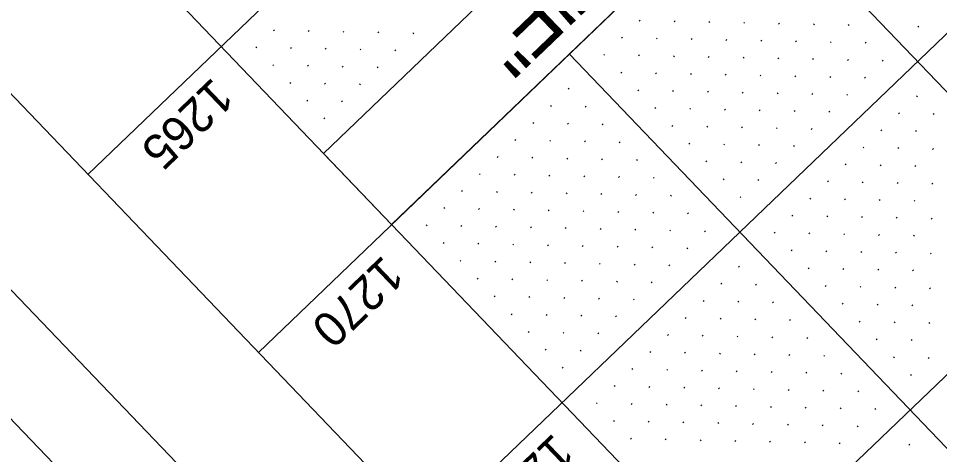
# Model space of a CAD drawing. Extents: x 2148987 to 2151117, y 142806 to 144993.
# Drawn here: x 2149110.7 to 2149297.8, y 143537.7 to 143626.2 of the extents above; entities that cross this region are included whole.
import ezdxf

# ---------------------------------------------------------------- set-up
doc = ezdxf.new("R2010")
doc.units = 0
for name, color, linetype in [('BASELINE', 7, 'Continuous'), ('PR_ABUT_PH3', 7, 'Continuous'), ('PR_PIER_PH3', 7, 'Continuous'), ('PR_Road_Concrete', 7, 'Continuous'), ('PR_Storm_Flow_Line', 7, 'Continuous'), ('SHT_Profile_Grid_Minor', 7, 'Continuous'), ('Wall D Bore', 7, 'Continuous')]:
    doc.layers.add(name, color=color, linetype=linetype)

msp = doc.modelspace()

# ---------------------------------------------------------------- linework, layer by layer
at = {"layer": 'BASELINE'}
msp.add_lwpolyline([(2151029.45, 144024.32), (2149802.07, 142848.08), (2149040.98, 143642.27), (2150268.36, 144818.51)], close=True, dxfattribs=at)
at = {"layer": 'PR_ABUT_PH3'}
msp.add_lwpolyline([(2151117.11, 144051.19), (2149817.52, 142805.76), (2148987.24, 143672.15), (2150286.82, 144917.58)], close=True, dxfattribs=at)
at = {"layer": 'PR_PIER_PH3'}
for p, q in [((2150261.97, 144684.26), (2149124.83, 143594.52)), ((2150296.56, 144648.16), (2149159.43, 143558.42)), ((2150331.16, 144612.07), (2149194.02, 143522.32)), ((2150365.75, 144575.97), (2149228.62, 143486.22)), ((2149258.7, 143653.55), (2149504.33, 143397.25)), ((2149222.6, 143618.96), (2149468.23, 143362.65))]:
    msp.add_line(p, q, dxfattribs=at)
at = {"layer": 'PR_Road_Concrete'}
msp.add_line((2149134.61, 143638.51), (2149463.26, 143295.57), dxfattribs=at)
for points in [[(2150941.76, 143974.91), (2149804.63, 142885.16), (2149078.13, 143643.25), (2150215.26, 144733)], [(2149294.8, 143688.15), (2149280.96, 143702.59), (2149172.66, 143598.8), (2149186.5, 143584.36)]]:
    msp.add_lwpolyline(points, close=True, dxfattribs=at)
at = {"layer": 'SHT_Profile_Grid_Minor'}
for p, q in [((2149236.98, 143625.81), (2149236.8, 143625.64)), ((2149244.05, 143625.66), (2149243.87, 143625.49)), ((2149251.12, 143625.51), (2149250.94, 143625.34)), ((2149258.19, 143625.36), (2149258.01, 143625.19)), ((2149265.26, 143625.21), (2149265.08, 143625.04)), ((2149272.33, 143625.06), (2149272.15, 143624.89)), ((2149279.4, 143624.91), (2149279.22, 143624.74)), ((2149293.54, 143624.61), (2149293.36, 143624.44)), ((2149162.68, 143623.86), (2149162.5, 143623.69)), ((2149169.75, 143623.71), (2149169.57, 143623.54)), ((2149176.82, 143623.56), (2149176.63, 143623.39)), ((2149183.88, 143623.41), (2149183.7, 143623.23)), ((2149190.95, 143623.26), (2149190.77, 143623.08)), ((2149233.37, 143622.35), (2149233.19, 143622.18)), ((2149240.44, 143622.2), (2149240.26, 143622.03)), ((2149247.51, 143622.05), (2149247.33, 143621.88)), ((2149254.58, 143621.9), (2149254.4, 143621.73)), ((2149261.65, 143621.75), (2149261.47, 143621.58)), ((2149268.72, 143621.6), (2149268.54, 143621.43)), ((2149275.79, 143621.45), (2149275.61, 143621.28)), ((2149282.86, 143621.3), (2149282.68, 143621.13)), ((2149159.07, 143620.4), (2149158.89, 143620.23)), ((2149166.14, 143620.25), (2149165.96, 143620.08)), ((2149173.21, 143620.1), (2149173.02, 143619.93)), ((2149180.27, 143619.95), (2149180.09, 143619.78)), ((2149187.34, 143619.8), (2149187.16, 143619.62)), ((2149229.76, 143618.89), (2149229.58, 143618.72)), ((2149236.83, 143618.74), (2149236.65, 143618.57)), ((2149243.9, 143618.59), (2149243.72, 143618.42)), ((2149250.97, 143618.44), (2149250.79, 143618.27)), ((2149258.04, 143618.29), (2149257.86, 143618.12)), ((2149265.11, 143618.14), (2149264.93, 143617.97)), ((2149272.18, 143617.99), (2149272, 143617.82)), ((2149279.25, 143617.84), (2149279.07, 143617.67)), ((2149286.32, 143617.69), (2149286.14, 143617.52)), ((2149162.53, 143616.79), (2149162.35, 143616.62)), ((2149169.6, 143616.64), (2149169.42, 143616.47)), ((2149176.66, 143616.49), (2149176.48, 143616.32)), ((2149183.73, 143616.34), (2149183.55, 143616.17)), ((2149233.22, 143615.29), (2149233.04, 143615.11)), ((2149240.29, 143615.13), (2149240.11, 143614.96)), ((2149247.36, 143614.98), (2149247.18, 143614.81)), ((2149254.43, 143614.83), (2149254.25, 143614.66)), ((2149261.5, 143614.68), (2149261.32, 143614.51)), ((2149268.57, 143614.53), (2149268.39, 143614.36)), ((2149275.64, 143614.38), (2149275.46, 143614.21)), ((2149282.71, 143614.23), (2149282.53, 143614.06)), ((2149165.99, 143613.18), (2149165.81, 143613.01)), ((2149173.06, 143613.03), (2149172.87, 143612.86)), ((2149180.12, 143612.88), (2149179.94, 143612.71)), ((2149222.54, 143611.98), (2149222.36, 143611.8)), ((2149236.68, 143611.68), (2149236.5, 143611.5)), ((2149243.75, 143611.52), (2149243.57, 143611.35)), ((2149169.45, 143609.57), (2149169.26, 143609.4)), ((2149250.82, 143611.37), (2149250.64, 143611.2)), ((2149257.89, 143611.22), (2149257.71, 143611.05)), ((2149264.96, 143611.07), (2149264.78, 143610.9)), ((2149272.03, 143610.92), (2149271.85, 143610.75)), ((2149279.1, 143610.77), (2149278.92, 143610.6)), ((2149293.24, 143610.47), (2149293.06, 143610.3)), ((2149176.51, 143609.42), (2149176.33, 143609.25)), ((2149218.93, 143608.52), (2149218.75, 143608.34)), ((2149226, 143608.37), (2149225.82, 143608.19)), ((2149240.14, 143608.07), (2149239.96, 143607.89)), ((2149247.21, 143607.91), (2149247.03, 143607.74)), ((2149254.28, 143607.76), (2149254.1, 143607.59)), ((2149172.9, 143605.96), (2149172.72, 143605.79)), ((2149261.35, 143607.61), (2149261.17, 143607.44)), ((2149268.42, 143607.46), (2149268.24, 143607.29)), ((2149275.49, 143607.31), (2149275.31, 143607.14)), ((2149289.63, 143607.01), (2149289.45, 143606.84)), ((2149296.7, 143606.86), (2149296.51, 143606.69)), ((2149215.32, 143605.06), (2149215.14, 143604.88)), ((2149222.39, 143604.91), (2149222.21, 143604.73)), ((2149229.46, 143604.76), (2149229.28, 143604.58)), ((2149243.6, 143604.46), (2149243.42, 143604.28)), ((2149250.67, 143604.3), (2149250.49, 143604.13)), ((2149257.74, 143604.15), (2149257.56, 143603.98)), ((2149264.81, 143604), (2149264.63, 143603.83)), ((2149271.88, 143603.85), (2149271.7, 143603.68)), ((2149286.02, 143603.55), (2149285.84, 143603.38)), ((2149293.09, 143603.4), (2149292.91, 143603.23)), ((2149211.71, 143601.6), (2149211.53, 143601.42)), ((2149218.78, 143601.45), (2149218.6, 143601.27)), ((2149225.85, 143601.3), (2149225.67, 143601.12)), ((2149232.92, 143601.15), (2149232.74, 143600.97)), ((2149247.06, 143600.85), (2149246.88, 143600.67)), ((2149254.13, 143600.69), (2149253.95, 143600.52)), ((2149261.2, 143600.54), (2149261.02, 143600.37)), ((2149268.27, 143600.39), (2149268.09, 143600.22)), ((2149282.41, 143600.09), (2149282.23, 143599.92)), ((2149289.48, 143599.94), (2149289.3, 143599.77)), ((2149296.55, 143599.79), (2149296.36, 143599.62)), ((2149208.1, 143598.14), (2149207.92, 143597.96)), ((2149215.17, 143597.99), (2149214.99, 143597.81)), ((2149222.24, 143597.84), (2149222.06, 143597.66)), ((2149229.31, 143597.69), (2149229.13, 143597.51)), ((2149236.38, 143597.54), (2149236.2, 143597.36)), ((2149250.52, 143597.24), (2149250.34, 143597.06)), ((2149257.59, 143597.08), (2149257.41, 143596.91)), ((2149264.66, 143596.93), (2149264.48, 143596.76)), ((2149278.8, 143596.63), (2149278.62, 143596.46)), ((2149285.87, 143596.48), (2149285.69, 143596.31)), ((2149204.49, 143594.68), (2149204.31, 143594.51)), ((2149292.94, 143596.33), (2149292.75, 143596.16)), ((2149211.56, 143594.53), (2149211.38, 143594.35)), ((2149218.63, 143594.38), (2149218.45, 143594.2)), ((2149225.7, 143594.23), (2149225.52, 143594.05)), ((2149232.77, 143594.08), (2149232.59, 143593.9)), ((2149239.84, 143593.93), (2149239.66, 143593.75)), ((2149253.98, 143593.63), (2149253.8, 143593.45)), ((2149261.05, 143593.47), (2149260.87, 143593.3)), ((2149275.19, 143593.17), (2149275.01, 143593)), ((2149282.26, 143593.02), (2149282.08, 143592.85)), ((2149289.33, 143592.87), (2149289.14, 143592.7)), ((2149296.39, 143592.72), (2149296.21, 143592.55)), ((2149200.88, 143591.22), (2149200.7, 143591.05)), ((2149207.95, 143591.07), (2149207.77, 143590.9)), ((2149215.02, 143590.92), (2149214.84, 143590.75)), ((2149222.09, 143590.77), (2149221.91, 143590.59)), ((2149229.16, 143590.62), (2149228.98, 143590.44)), ((2149236.23, 143590.47), (2149236.05, 143590.29)), ((2149243.3, 143590.32), (2149243.12, 143590.14)), ((2149257.44, 143590.02), (2149257.26, 143589.84)), ((2149271.58, 143589.71), (2149271.4, 143589.54)), ((2149278.65, 143589.56), (2149278.47, 143589.39)), ((2149285.72, 143589.41), (2149285.53, 143589.24)), ((2149292.78, 143589.26), (2149292.6, 143589.09)), ((2149197.27, 143587.76), (2149197.09, 143587.59)), ((2149204.34, 143587.61), (2149204.16, 143587.44)), ((2149211.41, 143587.46), (2149211.23, 143587.29)), ((2149218.48, 143587.31), (2149218.3, 143587.14)), ((2149225.55, 143587.16), (2149225.37, 143586.98)), ((2149232.62, 143587.01), (2149232.44, 143586.83)), ((2149239.69, 143586.86), (2149239.51, 143586.68)), ((2149246.76, 143586.71), (2149246.58, 143586.53)), ((2149267.97, 143586.25), (2149267.79, 143586.08)), ((2149275.04, 143586.1), (2149274.86, 143585.93)), ((2149282.11, 143585.95), (2149281.92, 143585.78)), ((2149289.17, 143585.8), (2149288.99, 143585.63)), ((2149296.24, 143585.65), (2149296.06, 143585.48)), ((2149193.66, 143584.3), (2149193.48, 143584.13)), ((2149200.73, 143584.15), (2149200.55, 143583.98)), ((2149207.8, 143584), (2149207.62, 143583.83)), ((2149214.87, 143583.85), (2149214.69, 143583.68)), ((2149221.94, 143583.7), (2149221.76, 143583.53)), ((2149229.01, 143583.55), (2149228.83, 143583.37)), ((2149236.08, 143583.4), (2149235.9, 143583.22)), ((2149243.15, 143583.25), (2149242.97, 143583.07)), ((2149250.22, 143583.1), (2149250.04, 143582.92)), ((2149264.36, 143582.8), (2149264.18, 143582.62)), ((2149271.43, 143582.65), (2149271.25, 143582.47)), ((2149278.5, 143582.49), (2149278.31, 143582.32)), ((2149285.56, 143582.34), (2149285.38, 143582.17)), ((2149292.63, 143582.19), (2149292.45, 143582.02)), ((2149197.12, 143580.69), (2149196.94, 143580.52)), ((2149204.19, 143580.54), (2149204.01, 143580.37)), ((2149211.26, 143580.39), (2149211.08, 143580.22)), ((2149218.33, 143580.24), (2149218.15, 143580.07)), ((2149225.4, 143580.09), (2149225.22, 143579.92)), ((2149232.47, 143579.94), (2149232.29, 143579.76)), ((2149239.54, 143579.79), (2149239.36, 143579.61)), ((2149246.61, 143579.64), (2149246.43, 143579.46)), ((2149267.82, 143579.19), (2149267.64, 143579.01)), ((2149274.89, 143579.04), (2149274.7, 143578.86)), ((2149281.95, 143578.88), (2149281.77, 143578.71)), ((2149289.02, 143578.73), (2149288.84, 143578.56)), ((2149296.09, 143578.58), (2149295.91, 143578.41)), ((2149200.58, 143577.08), (2149200.4, 143576.91)), ((2149207.65, 143576.93), (2149207.47, 143576.76)), ((2149214.72, 143576.78), (2149214.54, 143576.61)), ((2149221.79, 143576.63), (2149221.61, 143576.46)), ((2149228.86, 143576.48), (2149228.68, 143576.31)), ((2149235.93, 143576.33), (2149235.75, 143576.15)), ((2149243, 143576.18), (2149242.82, 143576)), ((2149257.14, 143575.88), (2149256.96, 143575.7)), ((2149271.28, 143575.58), (2149271.09, 143575.4)), ((2149278.34, 143575.43), (2149278.16, 143575.25)), ((2149285.41, 143575.27), (2149285.23, 143575.1)), ((2149292.48, 143575.12), (2149292.3, 143574.95)), ((2149204.04, 143573.47), (2149203.86, 143573.3)), ((2149211.11, 143573.32), (2149210.93, 143573.15)), ((2149218.18, 143573.17), (2149218, 143573)), ((2149225.25, 143573.02), (2149225.07, 143572.85)), ((2149232.32, 143572.87), (2149232.14, 143572.7)), ((2149239.39, 143572.72), (2149239.21, 143572.54)), ((2149253.53, 143572.42), (2149253.35, 143572.24)), ((2149260.6, 143572.27), (2149260.42, 143572.09)), ((2149274.73, 143571.97), (2149274.55, 143571.79)), ((2149281.8, 143571.82), (2149281.62, 143571.64)), ((2149288.87, 143571.66), (2149288.69, 143571.49)), ((2149295.94, 143571.51), (2149295.76, 143571.34)), ((2149207.5, 143569.86), (2149207.32, 143569.69)), ((2149214.57, 143569.71), (2149214.39, 143569.54)), ((2149221.64, 143569.56), (2149221.46, 143569.39)), ((2149228.71, 143569.41), (2149228.53, 143569.24)), ((2149235.78, 143569.26), (2149235.6, 143569.09)), ((2149249.92, 143568.96), (2149249.74, 143568.78)), ((2149256.99, 143568.81), (2149256.81, 143568.63)), ((2149264.06, 143568.66), (2149263.87, 143568.48)), ((2149278.19, 143568.36), (2149278.01, 143568.18)), ((2149285.26, 143568.21), (2149285.08, 143568.03)), ((2149292.33, 143568.05), (2149292.15, 143567.88)), ((2149210.96, 143566.25), (2149210.78, 143566.08)), ((2149218.03, 143566.1), (2149217.85, 143565.93)), ((2149225.1, 143565.95), (2149224.92, 143565.78)), ((2149232.17, 143565.8), (2149231.99, 143565.63)), ((2149246.31, 143565.5), (2149246.13, 143565.32)), ((2149253.38, 143565.35), (2149253.2, 143565.17)), ((2149260.45, 143565.2), (2149260.27, 143565.02)), ((2149267.51, 143565.05), (2149267.33, 143564.87)), ((2149281.65, 143564.75), (2149281.47, 143564.57)), ((2149288.72, 143564.6), (2149288.54, 143564.42)), ((2149295.79, 143564.44), (2149295.61, 143564.27)), ((2149214.42, 143562.64), (2149214.24, 143562.47)), ((2149221.49, 143562.49), (2149221.31, 143562.32)), ((2149228.56, 143562.34), (2149228.38, 143562.17)), ((2149242.7, 143562.04), (2149242.52, 143561.87)), ((2149249.77, 143561.89), (2149249.59, 143561.71)), ((2149256.84, 143561.74), (2149256.66, 143561.56)), ((2149263.91, 143561.59), (2149263.72, 143561.41)), ((2149270.97, 143561.44), (2149270.79, 143561.26)), ((2149285.11, 143561.14), (2149284.93, 143560.96)), ((2149292.18, 143560.99), (2149292, 143560.81)), ((2149217.88, 143559.03), (2149217.7, 143558.86)), ((2149224.95, 143558.88), (2149224.77, 143558.71)), ((2149239.09, 143558.58), (2149238.91, 143558.41)), ((2149246.16, 143558.43), (2149245.98, 143558.26)), ((2149253.23, 143558.28), (2149253.05, 143558.1)), ((2149260.3, 143558.13), (2149260.11, 143557.95)), ((2149267.36, 143557.98), (2149267.18, 143557.8)), ((2149274.43, 143557.83), (2149274.25, 143557.65)), ((2149288.57, 143557.53), (2149288.39, 143557.35)), ((2149295.64, 143557.38), (2149295.46, 143557.2)), ((2149221.34, 143555.42), (2149221.16, 143555.25)), ((2149235.48, 143555.12), (2149235.3, 143554.95)), ((2149242.55, 143554.97), (2149242.37, 143554.8)), ((2149249.62, 143554.82), (2149249.44, 143554.65)), ((2149256.69, 143554.67), (2149256.5, 143554.5)), ((2149263.75, 143554.52), (2149263.57, 143554.34)), ((2149270.82, 143554.37), (2149270.64, 143554.19)), ((2149277.89, 143554.22), (2149277.71, 143554.04)), ((2149292.03, 143553.92), (2149291.85, 143553.74)), ((2149231.87, 143551.66), (2149231.69, 143551.49)), ((2149238.94, 143551.51), (2149238.76, 143551.34)), ((2149246.01, 143551.36), (2149245.83, 143551.19)), ((2149253.08, 143551.21), (2149252.89, 143551.04)), ((2149260.14, 143551.06), (2149259.96, 143550.89)), ((2149267.21, 143550.91), (2149267.03, 143550.73)), ((2149274.28, 143550.76), (2149274.1, 143550.58)), ((2149281.35, 143550.61), (2149281.17, 143550.43)), ((2149228.26, 143548.2), (2149228.08, 143548.03)), ((2149235.33, 143548.05), (2149235.15, 143547.88)), ((2149242.4, 143547.9), (2149242.22, 143547.73)), ((2149249.47, 143547.75), (2149249.28, 143547.58)), ((2149256.53, 143547.6), (2149256.35, 143547.43)), ((2149263.6, 143547.45), (2149263.42, 143547.28)), ((2149270.67, 143547.3), (2149270.49, 143547.12)), ((2149277.74, 143547.15), (2149277.56, 143546.97)), ((2149284.81, 143547), (2149284.63, 143546.82)), ((2149231.72, 143544.59), (2149231.54, 143544.42)), ((2149238.79, 143544.44), (2149238.61, 143544.27)), ((2149245.86, 143544.29), (2149245.67, 143544.12)), ((2149252.92, 143544.14), (2149252.74, 143543.97)), ((2149259.99, 143543.99), (2149259.81, 143543.82)), ((2149267.06, 143543.84), (2149266.88, 143543.67)), ((2149274.13, 143543.69), (2149273.95, 143543.51)), ((2149281.2, 143543.54), (2149281.02, 143543.36)), ((2149235.18, 143540.98), (2149235, 143540.81)), ((2149242.25, 143540.83), (2149242.06, 143540.66)), ((2149249.31, 143540.68), (2149249.13, 143540.51)), ((2149256.38, 143540.53), (2149256.2, 143540.36)), ((2149263.45, 143540.38), (2149263.27, 143540.21)), ((2149270.52, 143540.23), (2149270.34, 143540.06)), ((2149277.59, 143540.08), (2149277.41, 143539.9)), ((2149291.73, 143539.78), (2149291.55, 143539.6))]:
    msp.add_line(p, q, dxfattribs=at)

# ---------------------------------------------------------------- texts
at = {"layer": 'PR_Storm_Flow_Line'}
msp.add_text('RAMP "F"', height=12, rotation=223.7809, dxfattribs=at).set_placement((2149254.9, 143672.07))
at = {"layer": 'Wall D Bore'}
for s, p in [('1265', (2149150.2, 143614.45)), ('1270', (2149184.79, 143578.35)), ('1275', (2149219.39, 143542.25))]:
    msp.add_text(s, height=7, rotation=223.7809, dxfattribs=at).set_placement(p)

doc.saveas('drawing.dxf')
